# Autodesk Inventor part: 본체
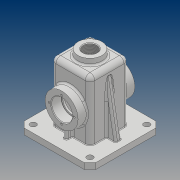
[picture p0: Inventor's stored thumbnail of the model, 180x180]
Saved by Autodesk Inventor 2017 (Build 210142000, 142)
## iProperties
Part Number: 본체
Material: 일반
Document SubType Name: Modeling
Designer: 20
Density: 1 g/cm^3
Appearance: 기본값
Author: 20
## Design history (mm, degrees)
sketch "스케치1"
  geometry: L1 (-32.5, 32.5)-(32.5, 32.5); L2 (32.5, 32.5)-(32.5, -32.5); L3 (32.5, -32.5)-(-32.5, -32.5); L4 (-32.5, -32.5)-(-32.5, 32.5); L5 (-32.5, 32.5)-(32.5, -32.5); L6 (32.5, 32.5)-(-32.5, -32.5); 1 further point
  constraints: 12 end point, 2 midpoint, 2 parallel, 1 horizontal, 1 perpendicular
  dimensions: "d0" = 65 distance of L2.end L3.end; "d1" = 65 distance of L1.end L2.end
extrude "돌출1" new body sketch "스케치1" stored distance "d2" = 110; taper "d3" = 0 deg
fillet "모깎기1" dims "d4" = 8
fillet "모깎기2" dims "d5" = 8
feature "쉘1" dims "d6" = 5
sketch "스케치2"
  geometry: L1 (60, -60)-(-60, -60); L2 (-60, -60)-(-60, 60); L3 (-60, 60)-(60, 60); L4 (60, 60)-(60, -60); L5 (60, -60)-(-60, 60); L6 (-60, -60)-(60, 60); L7 (24.5, -27.5)-(-24.5, -27.5) reference; L8 (27.5, 24.5)-(27.5, -24.5) reference; L9 (-24.5, 27.5)-(24.5, 27.5) reference; L10 (-27.5, -24.5)-(-27.5, 24.5) reference; A1 r 3 centre (24.5, -24.5) between (24.5, -27.5) and (27.5, -24.5) reference; A2 r 3 centre (24.5, 24.5) between (27.5, 24.5) and (24.5, 27.5) reference; A3 r 3 centre (-24.5, 24.5) between (-24.5, 27.5) and (-27.5, 24.5) reference; A4 r 3 centre (-24.5, -24.5) between (-27.5, -24.5) and (-24.5, -27.5) reference; 1 further point
  constraints: 12 end point, 2 midpoint, 2 parallel, 1 horizontal, 1 perpendicular
  dimensions: "d7" = 120 distance of L2.end L3.end; "d8" = 120 distance of L1.end L2.end
extrude "돌출2" join sketch "스케치2" distance "d9" = 10; taper "d10" = 0 deg
sketch "스케치3"
  geometry: C1 r 27.5 at (24.5, -47); 1 further point
  constraints: 1 centre point, 1 coincident
  dimensions: "d11" = 55 diameter of C1
extrude "돌출3" join sketch "스케치3" distance "d12" = 15; taper "d13" = 0 deg
sketch "스케치4"
  geometry: C1 r 17.5 at (0, 0); 1 further point
  constraints: 1 centre point, 1 coincident
  dimensions: "d14" = 35 diameter of C1
extrude "돌출4" cut sketch "스케치4" distance "d15" = 17; taper "d16" = 0 deg
sketch "스케치5"
  geometry: C1 r 15 at (0, 0); 1 further point
  constraints: 1 centre point, 1 coincident
  dimensions: "d17" = 30 diameter of C1
extrude "돌출5" cut sketch "스케치5" stored distance "d18" = 17; taper "d19" = 0 deg
sketch "스케치6"
  geometry: L1 (-32.5, -27.5)-(-47.5, -27.5) reference; L2 (60, -45)-(-60, -45) reference; L3 (-42.5, -27.5)-(-42.5, -45); L4 (-32.5, -12.49)-(-32.5, -45) reference; 1 further point
  constraints: 2 end point, 2 point on line, 1 vertical
  dimensions: "d20" = 10 distance between parallel lines of L4 L3
feature "리브1" sketch "스케치6" dims "d21" = 1, "d22" = 6, "d23" = 0, "d24" = 0, "d25" = 1, "d26" = 1
sketch "스케치7"
  geometry: L1 (-60, -45)-(60, -45) reference; L2 (48, -45)-(40.418, -2); L3 (60, -55)-(60, -45) reference; 1 further point
  constraints: 2 end point, 1 point on line
  dimensions: "d27" = 10 deg angle of L2 L3; "d28" = 12 distance from line of L2.start L3; "d29" = 43 vertical distance of L2.start L2.end
feature "리브2" sketch "스케치7" dims "d30" = 1, "d31" = 10, "d32" = 0, "d33" = 0, "d34" = 1, "d35" = 1
node "작업 평면1"
sketch "스케치8"
  geometry: C1 r 20 at (0, 0); 1 further point
  constraints: 1 centre point, 1 coincident
  dimensions: "d37" = 40 diameter of C1
extrude "돌출6" join sketch "스케치8" stored distance "d38" = 17; taper "d39" = 0 deg
hole "구멍1" diameter "d42" = 22.835; stored, may be unused: countersink angle "d46" = 90 deg, drill point angle "d48" = 118 deg; dims "d40" = 10, "d41" = 10, "d43" = 50, "d44" = 4, "d45" = 2, "d47" = 59.3
chamfer "모따기1" distance "d49" = 1; stored, may be unused: second distance "d50" = 2, angle "d51" = 45 deg
feature "면 기울기1" dims angle "d52" = 5 deg
sketch "스케치9"
  geometry: L1 (-60, -60)-(60, -60) reference; L2 (-60, 60)-(-60, -60) reference; C1 r 5 at (-47.5, -47.5); 1 further point
  constraints: 1 centre point
  dimensions: "d53" = 10 diameter of C1; "d54" = 12.5 distance from line of L1 C1.centre; "d55" = 12.5 distance from line of C1.centre L2
extrude "돌출7" cut sketch "스케치9" distance "d56" = 17; taper "d57" = 0 deg
chamfer "모따기2" distance "d58" = 10; stored, may be unused: second distance "d59" = 2, angle "d60" = 45 deg
fillet "모깎기3" dims "d67" = 3
fillet "모깎기4" dims "d68" = 3
fillet "모깎기5" dims "d69" = 1
fillet "모깎기6" dims "d70" = 3
node "작업 평면2"
sketch "스케치10"
  geometry: L1 (57, 0)-(57, 91) reference; L2 (4.5, -18)-(44.5, -18) reference; 2 further points
  constraints: 1 other
  dimensions: "d73" = 32.5 distance from line of point (24.5, 8) L1; "d74" = 26 distance from line of L2 point (24.5, 8)
feature "엠보싱1" sketch "스케치10" dims "d75" = 0.5, "d76" = 0
sketch "스케치11"
  geometry: 2 further points
  constraints: 1 vertical alignment
  dimensions: "d77" = 21 distance of point (0, 0) point (0, 21)
hole "구멍2" sketch "스케치11" at (0, 21) diameter "d78" = 3.242; stored, may be unused: countersink angle "d82" = 90 deg, drill point angle "d84" = 118 deg; dims "d79" = 8, "d80" = 4, "d81" = 2, "d83" = 10
fillet "모깎기8" dims "d88" = 0.3
fillet "모깎기9" dims "d89" = 3
node "솔리드1"
mirror "미러1"
mirror "미러2"
mirror "미러3"
pattern_linear "직사각형 패턴1" dims "d63" = 95, "d66" = 95
pattern_circular "원형 패턴1" dims angle "d86" = 360 deg
mirror "미러4"
